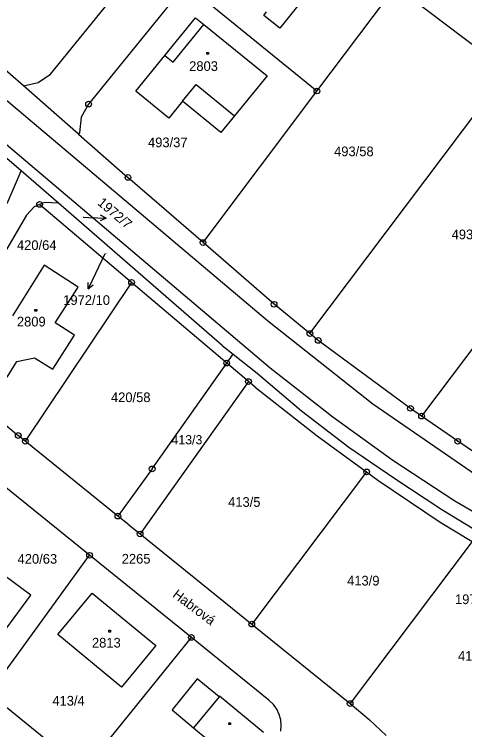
# Model space of a CAD drawing. Extents: x -795483 to -789093, y -1112258 to -1108741.
# Drawn here: x -791180.6 to -791101.5, y -1110903.8 to -1110778 of the extents above; entities that cross this region are included whole.
import ezdxf

# ---------------------------------------------------------------- set-up
doc = ezdxf.new("R2010")
doc.units = 0
for name, color, linetype in [('Komunikace', 7, 'Continuous'), ('Vrstva 1', 7, 'Continuous'), ('Vrstva 14', 7, 'Continuous'), ('Vrstva 15', 7, 'Continuous'), ('Vrstva 16', 7, 'Continuous'), ('Vrstva 2', 7, 'Continuous'), ('Vrstva 25', 7, 'Continuous'), ('Vrstva 28', 7, 'Continuous'), ('Vrstva 38', 7, 'Continuous')]:
    doc.layers.add(name, color=color, linetype=linetype)

msp = doc.modelspace()

# ---------------------------------------------------------------- linework, layer by layer
at = {"layer": 'Komunikace'}
for p, q in [((-791168.57, -1110813.67), (-791167.53, -1110813.72)), ((-791164.72, -1110820.1), (-791166.36, -1110823.56))]:
    msp.add_line(p, q, dxfattribs=at)
at = {"layer": 'Vrstva 1'}
for p, q in [((-791174.3, -1110788.56), (-791143.21, -1110750.2)), ((-791230.76, -1110759.67), (-791135.66, -1110840.14)), ((-791179.03, -1110790.61), (-791203.94, -1110768.8)), ((-791125.7, -1110770.1), (-791134, -1110780.47)), ((-791150.52, -1110772.76), (-791167.59, -1110793.8)), ((-791127.46, -1110791.5), (-791150.52, -1110772.76)), ((-791127.46, -1110791.5), (-791113.65, -1110773.14)), ((-791094.03, -1110788.01), (-791113.65, -1110773.14)), ((-791136.81, -1110778.22), (-791136.3, -1110777.56)), ((-791154.19, -1110785.23), (-791148.81, -1110778.64)), ((-791148.81, -1110778.64), (-791147.36, -1110779.79)), ((-791134, -1110780.47), (-791136.81, -1110778.22)), ((-791147.36, -1110779.79), (-791136.22, -1110788.85)), ((-791159.28, -1110791.55), (-791154.19, -1110785.23)), ((-791176.46, -1110790.01), (-791174.3, -1110788.56)), ((-791136.22, -1110788.85), (-791141.93, -1110795.86)), ((-791128.7, -1110834.15), (-791094.03, -1110788.01)), ((-791179.03, -1110790.61), (-791176.46, -1110790.01)), ((-791169.39, -1110799.06), (-791179.03, -1110790.61)), ((-791153.49, -1110796.26), (-791159.28, -1110791.55)), ((-791147.48, -1110818.15), (-791127.46, -1110791.5)), ((-791167.59, -1110793.8), (-791168.91, -1110796.07)), ((-791151.1, -1110793.31), (-791153.49, -1110796.26)), ((-791144.33, -1110798.8), (-791151.1, -1110793.31)), ((-791168.91, -1110796.07), (-791169.16, -1110798.85)), ((-791141.93, -1110795.86), (-791144.33, -1110798.8)), ((-791169.16, -1110798.85), (-791169.39, -1110799.06)), ((-791169.39, -1110799.06), (-791160.67, -1110806.69)), ((-791179.45, -1110805.56), (-791185.11, -1110800.68)), ((-791074.59, -1110802.74), (-791109.07, -1110848.65)), ((-791180.44, -1110807.85), (-791179.45, -1110805.56)), ((-791172.9, -1110811.2), (-791179.45, -1110805.56)), ((-791156.49, -1110810.32), (-791160.67, -1110806.69)), ((-791181.93, -1110811.3), (-791180.44, -1110807.85)), ((-791176.2, -1110811.44), (-791177.15, -1110811.84)), ((-791175.32, -1110811.07), (-791176.2, -1110811.44)), ((-791160.04, -1110825.15), (-791176.2, -1110811.44)), ((-791172.9, -1110811.2), (-791175.32, -1110811.07)), ((-791144.12, -1110836.21), (-791172.9, -1110811.2)), ((-791147.48, -1110818.15), (-791156.49, -1110810.32)), ((-791177.15, -1110811.84), (-791178.49, -1110813.33)), ((-791178.49, -1110813.33), (-791185.32, -1110824.9)), ((-791134.99, -1110829), (-791147.48, -1110818.15)), ((-791175.42, -1110822.12), (-791180.98, -1110831.02)), ((-791169.45, -1110825.96), (-791175.42, -1110822.12)), ((-791160.04, -1110825.15), (-791178.71, -1110853.07)), ((-791143.32, -1110839.33), (-791160.04, -1110825.15)), ((-791173.45, -1110832.26), (-791169.45, -1110825.96)), ((-791128.7, -1110834.15), (-791134.99, -1110829)), ((-791170.08, -1110834.43), (-791173.45, -1110832.26)), ((-791127.23, -1110835.35), (-791128.7, -1110834.15)), ((-791173.9, -1110840.41), (-791170.08, -1110834.43)), ((-791111.02, -1110847.29), (-791127.23, -1110835.35)), ((-791144.12, -1110836.21), (-791142.2, -1110837.74)), ((-791143.32, -1110839.33), (-791142.2, -1110837.74)), ((-791142.2, -1110837.74), (-791137.97, -1110841.1)), ((-791181.93, -1110841.81), (-791180.18, -1110839.07)), ((-791180.18, -1110839.07), (-791177.09, -1110838.4)), ((-791177.09, -1110838.4), (-791173.9, -1110840.41)), ((-791156.42, -1110857.94), (-791143.32, -1110839.33)), ((-791139.49, -1110842.58), (-791143.32, -1110839.33)), ((-791135.66, -1110840.14), (-791124.67, -1110848.8)), ((-791137.97, -1110841.1), (-791130.19, -1110847.75)), ((-791191.62, -1110842.33), (-791179.96, -1110852.06)), ((-791139.49, -1110842.58), (-791158.54, -1110869.37)), ((-791138.34, -1110843.55), (-791139.49, -1110842.58)), ((-791138.34, -1110843.55), (-791127.43, -1110852.12)), ((-791130.19, -1110847.75), (-791121.86, -1110854.09)), ((-791109.07, -1110848.65), (-791111.02, -1110847.29)), ((-791124.67, -1110848.8), (-791114.12, -1110856.39)), ((-791102.73, -1110853.08), (-791109.07, -1110848.65)), ((-791178.71, -1110853.07), (-791179.96, -1110852.06)), ((-791127.43, -1110852.12), (-791118.73, -1110858.46)), ((-791162.44, -1110866.23), (-791178.71, -1110853.07)), ((-791121.86, -1110854.09), (-791113.8, -1110859.61)), ((-791094.39, -1110858.69), (-791102.73, -1110853.08)), ((-791114.12, -1110856.39), (-791103.23, -1110863.52)), ((-791156.42, -1110857.94), (-791162.44, -1110866.23)), ((-791118.73, -1110858.46), (-791138.91, -1110885.22)), ((-791118.73, -1110858.46), (-791116.75, -1110859.9)), ((-791116.75, -1110859.9), (-791105.8, -1110867.3)), ((-791113.8, -1110859.61), (-791105.52, -1110865.09)), ((-791167.42, -1110873.12), (-791182.75, -1110860.74)), ((-791103.23, -1110863.52), (-791091.99, -1110870.19)), ((-791105.52, -1110865.09), (-791096.89, -1110870.33)), ((-791160.53, -1110867.77), (-791162.44, -1110866.23)), ((-791160.53, -1110867.77), (-791158.54, -1110869.37)), ((-791105.8, -1110867.3), (-791100.21, -1110870.69)), ((-791158.54, -1110869.37), (-791141.06, -1110883.48)), ((-791100.21, -1110870.69), (-791121.63, -1110899.19)), ((-791185.07, -1110897.43), (-791167.42, -1110873.12)), ((-791149.53, -1110887.57), (-791167.42, -1110873.12)), ((-791177.77, -1110880.13), (-791182.51, -1110876.64)), ((-791184.02, -1110888.62), (-791177.77, -1110880.13)), ((-791172.99, -1110887.07), (-791166.94, -1110879.75)), ((-791166.94, -1110879.75), (-791155.75, -1110888.96)), ((-791141.06, -1110883.48), (-791138.91, -1110885.22)), ((-791138.91, -1110885.22), (-791121.63, -1110899.19)), ((-791161.81, -1110896.29), (-791172.99, -1110887.07)), ((-791168.4, -1110910.9), (-791149.53, -1110887.57)), ((-791135.91, -1110898.56), (-791149.53, -1110887.57)), ((-791155.75, -1110888.96), (-791161.81, -1110896.29)), ((-791148.49, -1110894.84), (-791152.93, -1110900.28)), ((-791144.64, -1110897.99), (-791148.49, -1110894.84)), ((-791168.4, -1110910.9), (-791185.07, -1110897.43)), ((-791144.57, -1110897.91), (-791144.64, -1110897.99)), ((-791136.84, -1110904.27), (-791144.57, -1110897.91)), ((-791135.1, -1110899.36), (-791135.91, -1110898.56)), ((-791134.53, -1110900.18), (-791135.1, -1110899.36)), ((-791121.63, -1110899.19), (-791118.3, -1110902)), ((-791152.93, -1110900.28), (-791149.16, -1110903.48)), ((-791134.1, -1110901.09), (-791134.53, -1110900.18)), ((-791133.83, -1110902.04), (-791134.1, -1110901.09)), ((-791133.73, -1110903.04), (-791133.83, -1110902.04)), ((-791118.3, -1110902), (-791115.3, -1110904.8)), ((-791133.81, -1110904.04), (-791133.73, -1110903.04)), ((-791149.16, -1110903.48), (-791146.75, -1110905.47))]:
    msp.add_line(p, q, dxfattribs=at)
at = {"layer": 'Vrstva 16'}
for p, q in [((-791167.53, -1110813.72), (-791164.53, -1110813.85)), ((-791164.53, -1110813.85), (-791165.55, -1110814.31)), ((-791164.53, -1110813.85), (-791165.51, -1110813.31)), ((-791166.36, -1110823.56), (-791167.65, -1110826.27)), ((-791167.65, -1110826.27), (-791167.67, -1110825.15)), ((-791167.65, -1110826.27), (-791166.77, -1110825.58))]:
    msp.add_line(p, q, dxfattribs=at)
at = {"layer": 'Vrstva 2'}
for p, q in [((-791136.16, -1110831.91), (-791227.18, -1110755.16)), ((-791152.75, -1110786.43), (-791147.36, -1110779.79)), ((-791154.19, -1110785.23), (-791152.75, -1110786.43)), ((-791151.1, -1110793.31), (-791148.7, -1110790.36)), ((-791148.7, -1110790.36), (-791141.93, -1110795.86)), ((-791117.65, -1110846.57), (-791136.16, -1110831.91)), ((-791091.77, -1110864.38), (-791117.65, -1110846.57)), ((-791144.64, -1110897.99), (-791149.16, -1110903.48))]:
    msp.add_line(p, q, dxfattribs=at)
at = {"layer": 'Vrstva 25'}
for p, q in [((-791146.84, -1110784.75), (-791146.54, -1110784.75)), ((-791146.84, -1110785.05), (-791146.84, -1110784.75)), ((-791146.54, -1110785.05), (-791146.84, -1110785.05)), ((-791146.54, -1110784.75), (-791146.54, -1110785.05)), ((-791177.01, -1110829.91), (-791176.71, -1110829.91)), ((-791177.01, -1110830.21), (-791177.01, -1110829.91)), ((-791176.71, -1110830.21), (-791177.01, -1110830.21)), ((-791176.71, -1110829.91), (-791176.71, -1110830.21)), ((-791164.02, -1110886.31), (-791163.72, -1110886.31)), ((-791164.02, -1110886.61), (-791164.02, -1110886.31)), ((-791163.72, -1110886.61), (-791164.02, -1110886.61)), ((-791163.72, -1110886.31), (-791163.72, -1110886.61)), ((-791142.93, -1110902.59), (-791142.63, -1110902.59)), ((-791142.93, -1110902.89), (-791142.93, -1110902.59)), ((-791142.63, -1110902.89), (-791142.93, -1110902.89)), ((-791142.63, -1110902.59), (-791142.63, -1110902.89))]:
    msp.add_line(p, q, dxfattribs=at)
at = {"layer": 'Vrstva 28'}
for centre, radius in [((-791127.46, -1110791.5), 0.5), ((-791127.46, -1110791.5), 0.01), ((-791167.59, -1110793.8), 0.5), ((-791167.59, -1110793.8), 0.01), ((-791160.67, -1110806.69), 0.5), ((-791160.67, -1110806.69), 0.01), ((-791176.2, -1110811.44), 0.5), ((-791176.2, -1110811.44), 0.01), ((-791147.48, -1110818.15), 0.5), ((-791147.48, -1110818.15), 0.01), ((-791160.04, -1110825.15), 0.5), ((-791160.04, -1110825.15), 0.01), ((-791134.99, -1110829), 0.5), ((-791134.99, -1110829), 0.01), ((-791128.7, -1110834.15), 0.5), ((-791128.7, -1110834.15), 0.01), ((-791127.23, -1110835.35), 0.5), ((-791127.23, -1110835.35), 0.01), ((-791143.32, -1110839.33), 0.5), ((-791143.32, -1110839.33), 0.01), ((-791139.49, -1110842.58), 0.5), ((-791139.49, -1110842.58), 0.01), ((-791111.02, -1110847.29), 0.5), ((-791111.02, -1110847.29), 0.01), ((-791109.07, -1110848.65), 0.5), ((-791109.07, -1110848.65), 0.01), ((-791179.96, -1110852.06), 0.5), ((-791179.96, -1110852.06), 0.01), ((-791178.71, -1110853.07), 0.5), ((-791102.73, -1110853.08), 0.5), ((-791178.71, -1110853.07), 0.01), ((-791102.73, -1110853.08), 0.01), ((-791156.42, -1110857.94), 0.5), ((-791156.42, -1110857.94), 0.01), ((-791118.73, -1110858.46), 0.5), ((-791118.73, -1110858.46), 0.01), ((-791162.44, -1110866.23), 0.5), ((-791162.44, -1110866.23), 0.01), ((-791158.54, -1110869.37), 0.5), ((-791158.54, -1110869.37), 0.01), ((-791167.42, -1110873.12), 0.5), ((-791167.42, -1110873.12), 0.01), ((-791138.91, -1110885.22), 0.5), ((-791138.91, -1110885.22), 0.01), ((-791149.53, -1110887.57), 0.5), ((-791149.53, -1110887.57), 0.01), ((-791121.63, -1110899.19), 0.5), ((-791121.63, -1110899.19), 0.01)]:
    msp.add_circle(centre, radius, dxfattribs=at)

# ---------------------------------------------------------------- texts
at = {"layer": 'Vrstva 14'}
for s, height, p in [('493/37', 1.7, (-791157.15, -1110801.38)), ('493/58', 1.7, (-791124.45, -1110802.96)), ('1972/7', 0.1, (-791168.81, -1110813.67)), ('493/1', 1.7, (-791103.79, -1110817.56)), ('420/64', 1.7, (-791180.18, -1110819.44)), ('1972/10', 0.1, (-791164.72, -1110820.1)), ('420/58', 1.7, (-791163.66, -1110846.19)), ('413/3', 1.62, (-791153.02, -1110853.62)), ('413/5', 1.7, (-791143.07, -1110864.6)), ('420/63', 1.7, (-791180.07, -1110874.6)), ('2265', 1.7, (-791161.77, -1110874.58)), ('413/9', 1.7, (-791122.16, -1110878.43)), ('413/8', 1.7, (-791102.67, -1110891.66)), ('413/4', 1.7, (-791173.96, -1110899.54))]:
    msp.add_text(s, height=height, dxfattribs=at).set_placement(p)
at = {"layer": 'Vrstva 15'}
for s, p in [('2803', (-791149.92, -1110787.97)), ('2809', (-791180.19, -1110832.89)), ('2813', (-791167, -1110889.34))]:
    msp.add_text(s, height=1.7, dxfattribs=at).set_placement(p)
at = {"layer": 'Vrstva 16'}
msp.add_text('1972/7', height=1.7, rotation=319.6767, dxfattribs=at).set_placement((-791166.16, -1110811.37))
for s, p in [('1972/10', (-791172.05, -1110829.1)), ('1972/11', (-791103.2, -1110881.7))]:
    msp.add_text(s, height=1.7, dxfattribs=at).set_placement(p)
at = {"layer": 'Vrstva 38'}
msp.add_text('Habrová', height=1.7, rotation=322.9246, dxfattribs=at).set_placement((-791152.97, -1110880.33))

doc.saveas('drawing.dxf')
